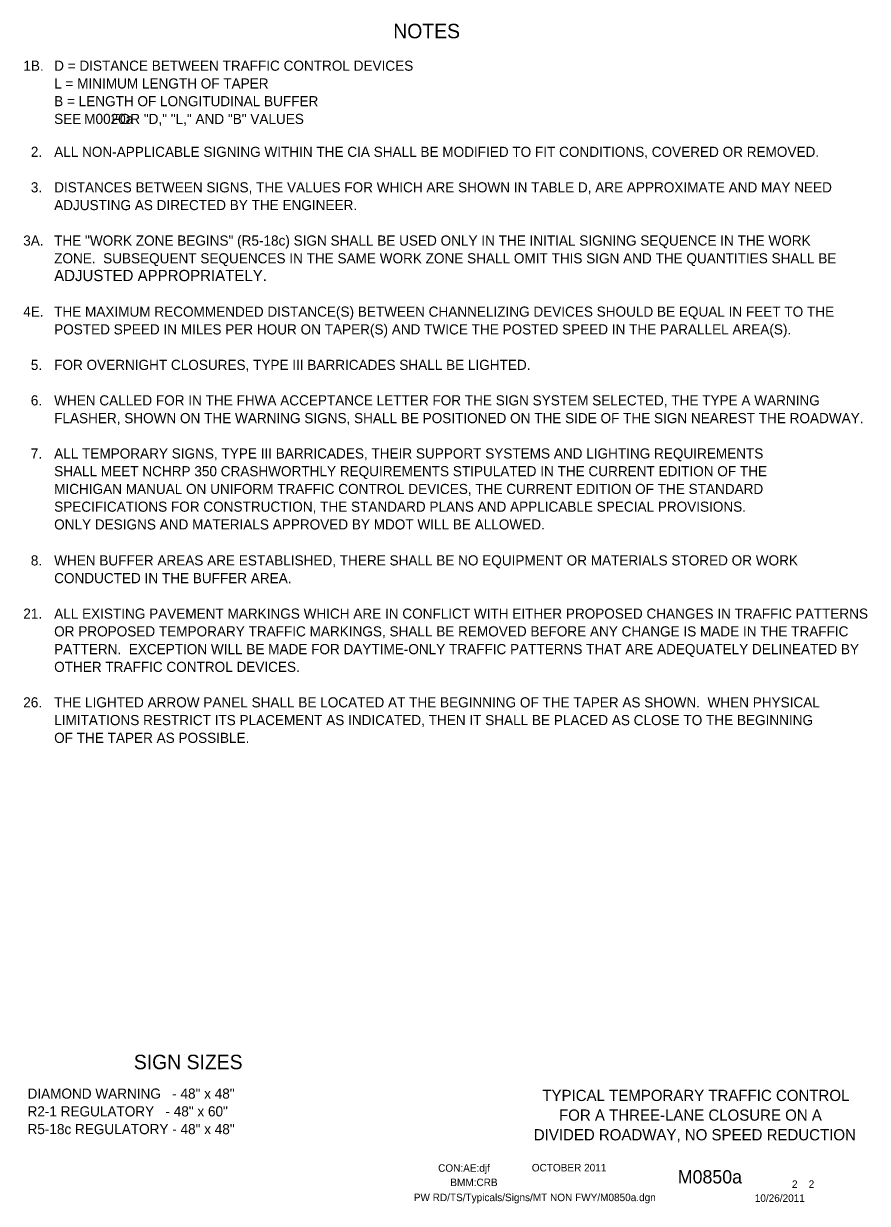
# Model space of a CAD drawing. Extents: x 16742 to 18475, y 7016 to 8203.
# Drawn here: x 17776 to 18475, y 7218 to 8195 of the extents above; entities that cross this region are included whole.
import ezdxf

# ---------------------------------------------------------------- set-up
doc = ezdxf.new("R2010")
doc.units = 0
for name, color, linetype in [('BORDER', 7, 'Continuous'), ('BORDER_SIGNAL_WO', 7, 'Continuous'), ('TYPICAL_TEXT_DIMEN_PR', 7, 'Continuous')]:
    doc.layers.add(name, color=color, linetype=linetype)

msp = doc.modelspace()

# ---------------------------------------------------------------- linework, layer by layer
at = {"layer": 'BORDER'}
msp.add_line((17909.25, 7341.25), (17909.25, 7341.25), dxfattribs=at)
msp.add_line((17909.25, 7341.25), (17909.25, 7341.25), dxfattribs=at)

# ---------------------------------------------------------------- texts
for s, p in [('TYPICAL TEMPORARY TRAFFIC CONTROL', (18206.02, 7302.9)), ('FOR A THREE-LANE CLOSURE ON A', (18219.84, 7286.6)), ('DIVIDED ROADWAY, NO SPEED REDUCTION', (18198.96, 7270.3))]:
    msp.add_text(s, height=9.3, dxfattribs=at).set_placement(p)
at = {"layer": 'BORDER_SIGNAL_WO'}
for s, height, p in [('CON:AE:djf', 6.2, (18119.69, 7244.31)), ('    OCTOBER 2011    ', 6.2, (18188.08, 7244.59)), ('    M0850a   ', 11, (18301.86, 7234.63)), ('BMM:CRB   ', 6.2, (18129.81, 7232.42)), (' 2    2 ', 6.2, (18410.45, 7230.95)), ('PW RD/TS/Typicals/Signs/MT NON FWY/M0850a.dgn    ', 6.2, (18099.55, 7219.96)), ('10/26/2011    ', 6.2, (18381.93, 7219.38))]:
    msp.add_text(s, height=height, dxfattribs=at).set_placement(p)
at = {"layer": 'TYPICAL_TEXT_DIMEN_PR'}
for s, height, p in [('NOTES', 12, (18082.55, 8183.25)), ('1B.', 8.4, (17776.19, 8156.36)), ('D = DISTANCE BETWEEN TRAFFIC CONTROL DEVICES', 8.4, (17801.7, 8156.36)), ('L = MINIMUM LENGTH OF TAPER', 8.4, (17801.7, 8141.66)), ('B = LENGTH OF LONGITUDINAL BUFFER', 8.4, (17801.7, 8126.96)), ('SEE        FOR "D," "L," AND "B" VALUES', 8.4, (17801.7, 8112.26)), ('M0020a', 8.4, (17826.62, 8112.26)), ('2.', 8.4, (17782.39, 8085)), ('ALL NON-APPLICABLE SIGNING WITHIN THE CIA SHALL BE MODIFIED TO FIT CONDITIONS, COVERED OR REMOVED.', 8.4, (17801.7, 8085)), ('3.', 8.4, (17782.39, 8055.6)), ('DISTANCES BETWEEN SIGNS, THE VALUES FOR WHICH ARE SHOWN IN TABLE D, ARE APPROXIMATE AND MAY NEED', 8.4, (17801.7, 8055.6)), ('ADJUSTING AS DIRECTED BY THE ENGINEER.', 8.4, (17801.7, 8040.9)), ('3A.', 8.4, (17776.09, 8011.5)), ('THE "WORK ZONE BEGINS" (R5-18c) SIGN SHALL BE USED ONLY IN THE INITIAL SIGNING SEQUENCE IN THE WORK', 8.4, (17801.7, 8011.5)), ('ZONE.  SUBSEQUENT SEQUENCES IN THE SAME WORK ZONE SHALL OMIT THIS SIGN AND THE QUANTITIES SHALL BE', 8.4, (17801.7, 7996.8)), ('ADJUSTED APPROPRIATELY.', 9.3, (17801.7, 7982.1)), ('4E.', 8.4, (17776.13, 7952.62)), ('THE MAXIMUM RECOMMENDED DISTANCE(S) BETWEEN CHANNELIZING DEVICES SHOULD BE EQUAL IN FEET TO THE', 8.4, (17801.7, 7952.62)), ('POSTED SPEED IN MILES PER HOUR ON TAPER(S) AND TWICE THE POSTED SPEED IN THE PARALLEL AREA(S).', 8.4, (17801.7, 7937.92)), ('5.', 8.4, (17782.39, 7908.52)), ('FOR OVERNIGHT CLOSURES, TYPE III BARRICADES SHALL BE LIGHTED.', 8.4, (17801.7, 7908.52)), ('6.', 8.4, (17782.34, 7879.12)), ('WHEN CALLED FOR IN THE FHWA ACCEPTANCE LETTER FOR THE SIGN SYSTEM SELECTED, THE TYPE A WARNING ', 8.4, (17801.7, 7879.12)), ('FLASHER, SHOWN ON THE WARNING SIGNS, SHALL BE POSITIONED ON THE SIDE OF THE SIGN NEAREST THE ROADWAY.', 8.4, (17801.7, 7864.42)), ('7.', 8.4, (17782.34, 7835.12)), ('ALL TEMPORARY SIGNS, TYPE III BARRICADES, THEIR SUPPORT SYSTEMS AND LIGHTING REQUIREMENTS', 8.4, (17801.7, 7835.15)), ('SHALL MEET NCHRP 350 CRASHWORTHLY REQUIREMENTS STIPULATED IN THE CURRENT EDITION OF THE', 8.4, (17801.7, 7820.44)), ('MICHIGAN MANUAL ON UNIFORM TRAFFIC CONTROL DEVICES, THE CURRENT EDITION OF THE STANDARD', 8.4, (17801.7, 7805.74)), ('SPECIFICATIONS FOR CONSTRUCTION, THE STANDARD PLANS AND APPLICABLE SPECIAL PROVISIONS.', 8.4, (17801.7, 7791.05)), ('ONLY DESIGNS AND MATERIALS APPROVED BY MDOT WILL BE ALLOWED.', 8.4, (17801.7, 7776.35)), ('8.', 8.4, (17782.39, 7746.56)), ('WHEN BUFFER AREAS ARE ESTABLISHED, THERE SHALL BE NO EQUIPMENT OR MATERIALS STORED OR WORK     ', 8.4, (17801.7, 7746.56)), ('CONDUCTED IN THE BUFFER AREA.', 8.4, (17801.7, 7731.86)), ('21.', 8.4, (17776.14, 7702.46)), ('ALL EXISTING PAVEMENT MARKINGS WHICH ARE IN CONFLICT WITH EITHER PROPOSED CHANGES IN TRAFFIC PATTERNS', 8.4, (17801.7, 7702.46)), ('OR PROPOSED TEMPORARY TRAFFIC MARKINGS, SHALL BE REMOVED BEFORE ANY CHANGE IS MADE IN THE TRAFFIC', 8.4, (17801.7, 7687.76)), ('PATTERN.  EXCEPTION WILL BE MADE FOR DAYTIME-ONLY TRAFFIC PATTERNS THAT ARE ADEQUATELY DELINEATED BY', 8.4, (17801.7, 7673.06)), ('OTHER TRAFFIC CONTROL DEVICES.', 8.4, (17801.7, 7658.36)), ('26.', 8.4, (17776.09, 7628.96)), ('THE LIGHTED ARROW PANEL SHALL BE LOCATED AT THE BEGINNING OF THE TAPER AS SHOWN.  WHEN PHYSICAL', 8.4, (17801.7, 7628.96)), ('LIMITATIONS RESTRICT ITS PLACEMENT AS INDICATED, THEN IT SHALL BE PLACED AS CLOSE TO THE BEGINNING', 8.4, (17801.7, 7614.26)), ('OF THE TAPER AS POSSIBLE.', 8.4, (17801.7, 7599.56)), ('SIGN SIZES', 12, (17867.69, 7329.25)), ('DIAMOND WARNING   - 48" x 48"', 8.4, (17779.65, 7304.85)), ('R2-1 REGULATORY   - 48" x 60"', 8.4, (17779.65, 7290.15)), ('R5-18c REGULATORY - 48" x 48"', 8.4, (17779.65, 7275.45))]:
    msp.add_text(s, height=height, dxfattribs=at).set_placement(p)

doc.saveas('drawing.dxf')
